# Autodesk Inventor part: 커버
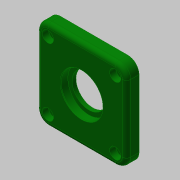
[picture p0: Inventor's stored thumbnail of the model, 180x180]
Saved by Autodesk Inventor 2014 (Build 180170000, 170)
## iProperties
Created: 2019-09
Part Number: 커버
Material: 알루미늄 6061
Document SubType Name: Modeling
Designer: mduedu
Density: 1 g/cm^3
Appearance: 진녹색
d1: 9.000 mm
d2: 0.00 deg
d3: 42.000 mm
d4: 3.000 mm
d5: 0.00 deg
d8: 24.000 mm
d10: 30.000 mm
d11: 5.200 mm
d17: 37.000 mm
d22: 4.000 mm
d24: 3.000 mm
d25: 3.000 mm
d27: 0.500 mm
d29: 30.00 deg
d30: 1.000 mm
d44: 64.000 mm
d45: 64.000 mm
d48: 8.000 mm
d49: 4.500 mm
d51: 8.000 mm
d52: 4.400 mm
Author: mduedu
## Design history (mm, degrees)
sketch "스케치1"
  geometry: L1 (-32, -32)-(32, -32); L2 (32, -32)-(32, 32); L3 (32, 32)-(-32, 32); L4 (-32, 32)-(-32, -32); L5 (-32, -32)-(32, 32); L6 (32, -32)-(-32, 32); 1 further point
  constraints: 12 end point, 2 midpoint, 2 parallel, 1 horizontal, 1 perpendicular
  dimensions: "d44" = 64 distance of L3.end L2.end; "d45" = 64 distance of L2.end L1.end
extrude "돌출1" new body sketch "스케치1" distance "d1" = 9; taper "d2" = 0 deg
sketch "스케치2"
  geometry: C1 r 21 at (0, 0); 1 further point
  constraints: 1 centre point, 1 coincident
  dimensions: "d3" = 42 diameter of C1
extrude "돌출2" join sketch "스케치2" distance "d4" = 3; taper "d5" = 0 deg
hole "구멍1" diameter "d8" = 24; stored, may be unused: countersink angle "d12" = 90 deg, drill point angle "d14" = 118 deg; dims "d9" = 6, "d10" = 30, "d11" = 5.2, "d13" = 8, "d46" = 10, "d47" = 10
hole "구멍2" diameter "d17" = 37; stored, may be unused: countersink angle "d21" = 90 deg, drill point angle "d23" = 0 deg; dims "d15" = 10, "d16" = 10, "d18" = 6, "d19" = 30, "d20" = 5.2, "d22" = 4
fillet "모깎기1" dims "d24" = 3
fillet "모깎기4" dims "d48" = 8
fillet "모깎기2" dims "d25" = 3
chamfer "모따기1" distance "d27" = 0.5; stored, may be unused: second distance "d28" = 2, angle "d29" = 30 deg
chamfer "모따기2" distance "d30" = 1; stored, may be unused: second distance "d31" = 2, angle "d32" = 30 deg
sketch "스케치4"
  geometry: A1 r 8 centre (-24, 24) between (-24, 32) and (-32, 24) reference; A2 r 8 centre (24, 24) between (32, 24) and (24, 32) reference; A3 r 8 centre (24, -24) between (24, -32) and (32, -24) reference; A4 r 8 centre (-24, -24) between (-32, -24) and (-24, -32) reference; 5 further points
  constraints: 4 coincident
hole "구멍4" sketch "스케치4" at (-24, 24), (24, 24), (24, -24), (-24, -24) diameter "d49" = 4.5; stored, may be unused: countersink angle "d53" = 90 deg, drill point angle "d55" = 118 deg; dims "d50" = 6, "d51" = 8, "d52" = 4.4, "d54" = 8
node "솔리드1"
